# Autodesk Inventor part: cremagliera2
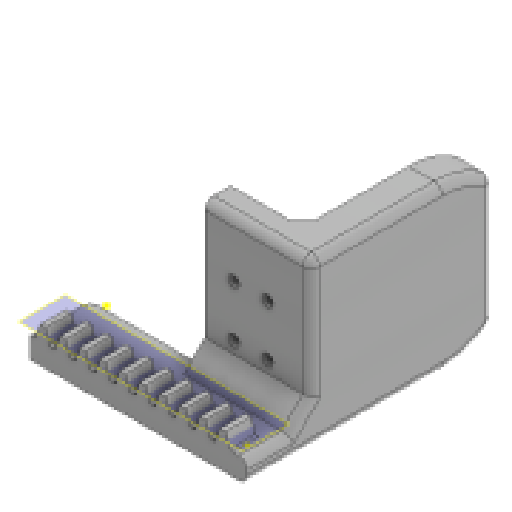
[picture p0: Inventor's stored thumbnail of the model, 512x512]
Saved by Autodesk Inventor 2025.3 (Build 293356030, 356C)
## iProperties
Created: 2025-12
Part Number: cremagliera2
Material: Generico
Document SubType Name: Modeling
Designer: R5800u
Density: 1 g/cm^3
Appearance: Grigio scuro
Author: R5800u
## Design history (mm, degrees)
sketch "Schizzo1"
  geometry: L1 (0, 1.875)-(1.178, 1.875); L2 (0, 0.375)-(1.679, 0.375); L3 (0.632, 3.375)-(1.86, 0); L4 (0.632, 3.375)-(1.178, 3.375); L5 (0, 0)-(0, 5.404); L6 (1.178, 1.875)-(1.178, 3.375); L7 (0, 3.375)-(0.632, 3.375); L8 (0, 1.875)-(-1.178, 1.875); L9 (0, 0.375)-(-1.679, 0.375); L10 (-0.632, 3.375)-(-1.86, 0); L11 (-0.632, 3.375)-(-1.178, 3.375); L12 (-1.178, 1.875)-(-1.178, 3.375); L13 (0, 3.375)-(-0.632, 3.375); L14 (-1.86, 0)-(1.86, 0); L15 (-1.86, 0)-(28.14, 0); L16 (28.14, 0)-(28.14, -5); L17 (28.14, -5)-(-1.86, -5); L18 (-1.86, -5)-(-1.86, 0)
  constraints: 36 end point, 5 point on line, 5 symmetric about line, 4 horizontal, 4 parallel, 2 perpendicular
  dimensions: "d0" = 3.375 distance of L7.start L5.start; "d2" = 1.5 distance between parallel lines of L1 L2; "d3" = 70 deg angle of L3 L4; "d5" = 1.178 distance between parallel lines of L5 L6; "d8" = 30 distance of L16.end L17.end; "d9" = 5 distance of L15.end L16.end
extrude "Estrusione1" new body sketch "Schizzo1" stored distance "d6" = 6; taper "d7" = 0 deg
sketch "Schizzo2"
  geometry: L1 (-1.86, 0)-(1.86, 0) reference; L2 (-1.86, 0)-(45.14, 0); L3 (45.14, 0)-(45.14, -5); L4 (45.14, -5)-(-1.86, -5); L5 (-1.86, -5)-(-1.86, 0); L6 (-1.86, 0)-(-2.86, 0); L7 (-2.86, 0)-(-2.86, -5); L8 (-2.86, -5)-(-1.86, -5); L9 (-1.86, -5)-(-1.86, 0); 3 further points
  constraints: 16 end point, 4 parallel, 2 horizontal, 2 perpendicular
  dimensions: "d10" = 47 distance of L3.end L4.end; "d11" = 5 distance of L2.end L3.end; "d14" = 1 distance of L8.end L7.end
extrude "Estrusione2" join sketch "Schizzo2" stored distance "d12" = 6; taper "d13" = 0 deg
fillet "Raccordo1" dims "d15" = 0.57
pattern_linear "Serie rettangolare1" dims "d18" = 4.71239
sketch "Schizzo3"
  geometry: L1 (-2.86, 1.875)-(45.14, 1.875); L2 (43.044, 3.375)-(41.779, 3.375) reference; 1 further point
  constraints: 2 end point, 1 horizontal
  dimensions: "d19" = 1.5 distance between parallel lines of L2 L1
node "Piano di lavoro1"
node "Piano di lavoro2"
sketch "Schizzo12"
  geometry: L1 (-45.14, -5)-(2.86, -5) reference; L2 (-45.14, -5)-(-23.14, -5); L3 (-23.14, -5)-(-23.14, 0); L4 (-23.14, 0)-(-45.14, 0); L5 (-45.14, 0)-(-45.14, -5); 2 further points
  constraints: 8 end point, 2 parallel, 1 horizontal, 1 perpendicular
  dimensions: "d118" = 22 distance between parallel lines of L5 L3
node "Piano di lavoro3"
extrude "Estrusione7" join sketch "Schizzo12" stored distance "d116" = 6; taper "d117" = 0 deg
sketch "Schizzo13"
  geometry: 1 further point
sketch "Schizzo14"
  geometry: L1 (0, 27.375)-(0.9, 27.375) reference; L2 (0, 26.375)-(0, 27.375) reference; L3 (0, 0)-(0, 5) reference; L4 (22, 0)-(0, 0) reference; L5 (22, 5)-(22, 0) reference; L6 (0, 5)-(22, 5) reference; L7 (22, 0)-(0, 0); L8 (0, 0)-(0, 38); L9 (0, 38)-(22, 38); L10 (22, 38)-(22, 0); 5 further points
  constraints: 8 end point, 2 parallel, 1 horizontal, 1 perpendicular
  dimensions: "d128" = 38 distance of L7.end L8.end
extrude "Estrusione8" join sketch "Schizzo14" distance "d119" = 6; taper "d120" = 0 deg
chamfer "Smusso16" distance "d121" = 5; stored, may be unused: second distance "d122" = 2, angle "d123" = 45 deg
sketch "Schizzo16"
  geometry: L1 (48, 0)-(48, -21.1) reference; L2 (0, 0)-(48, 0) reference; L3 (0, 0)-(0, -6) reference; L4 (26, -6)-(0, -6) reference; L5 (26, -6)-(26, -21.1) reference; L6 (48, -21.1)-(26, -21.1) reference; L7 (0, -6)-(0, -14); L8 (0, -14)-(26, -14); 1 further point
  constraints: 4 end point, 1 perpendicular, 1 point on line, 1 vertical
  dimensions: "d129" = 8 distance of L3.end L7.end
extrude "Estrusione10" join sketch "Schizzo16" distance "d130" = 5; taper "d131" = 0 deg
fillet "Raccordo3" dims "d132" = 2
sketch "Schizzo17"
  geometry: 1 further point
sketch "Schizzo18"
  geometry: C1 r 1.2 at (15.25, 24.875) reference; C2 r 1.2 at (7.25, 24.875) reference; C3 r 1.2 at (7.25, 12.875) reference; C4 r 1.2 at (15.25, 12.875) reference; 1 further point
hole "Foro5" sketch "Schizzo18" at (15.25, 24.875), (7.25, 24.875), (7.25, 12.875), (15.25, 12.875) diameter "d133" = 2.7; stored, may be unused: countersink angle "d137" = 90 deg, drill point angle "d139" = 118 deg; dims "d134" = 6, "d135" = 4.5, "d136" = 2.9, "d138" = 8
sketch "Schizzo19"
  geometry: L1 (10.1, 5)-(0, 5) reference; L2 (0, 0)-(0, 5) reference; L3 (0, 0)-(21.1, 0) reference; L4 (21.1, 38)-(21.1, 0) reference; L5 (15.1, 38)-(21.1, 38) reference; L6 (15.1, 38)-(15.1, 10) reference; L7 (10.1, 5)-(15.1, 10) reference; 1 further point
extrude "Estrusione11" join sketch "Schizzo19" distance "d140" = 3; taper "d141" = 0 deg
sketch "Schizzo20"
  geometry: L1 (22, 0)-(22, 38) reference; L2 (22, 38)-(-3, 38) reference; L3 (-3, 0)-(-3, 38) reference; L4 (22, 0)-(-3, 0) reference; L5 (22, 38)-(-3, 38) reference; L6 (-3, 0)-(5, 0); L7 (5, 0)-(5, 38); L8 (5, 38)-(-3, 38); L9 (-3, 38)-(-3, 0); C1 r 2.25 at (15.25, 12.875) reference; C2 r 2.25 at (7.25, 12.875) reference; C3 r 2.25 at (7.25, 24.875) reference; C4 r 2.25 at (15.25, 24.875) reference; 3 further points
  constraints: 8 end point, 2 parallel, 1 horizontal, 1 perpendicular, 1 point on line
extrude "Estrusione12" join sketch "Schizzo20" distance "d142" = 30; taper "d143" = 0 deg
chamfer "Smusso17" distance "d144" = 3; stored, may be unused: second distance "d145" = 2, angle "d146" = 45 deg
sketch "Schizzo21"
  geometry: L1 (51.1, 0)-(51.1, 38) reference; L2 (63.1, 33.731)-(63.1, 4.269); A1 r 19 centre (51.1, 19) between (51.1, 0) and (63.1, 33.731); 2 further points
  constraints: 3 point on circle, 2 end point, 1 centre point, 1 midpoint, 1 vertical
  dimensions: "d147" = 12 distance between parallel lines of L1 L2
extrude "Estrusione13" join sketch "Schizzo21" stored distance "d148" = 25; taper "d149" = 0 deg
fillet "Raccordo4" dims "d150" = 2
fillet "Raccordo5" dims "d151" = 2
chamfer "Smusso18" distance "d152" = 1; stored, may be unused: second distance "d153" = 2, angle "d154" = 45 deg
node "Solido1"
node "Riferimento5"
node "Riferimento6"
node "Linea chiusa proiettata1"
node "Linea chiusa proiettata3"
node "Riferimento7"
node "Riferimento8"
node "Riferimento9"
node "Riferimento10"
node "Linea chiusa proiettata4"
node "Linea chiusa proiettata5"
other parameters: "d1" = 1.5, "d20" = 0
